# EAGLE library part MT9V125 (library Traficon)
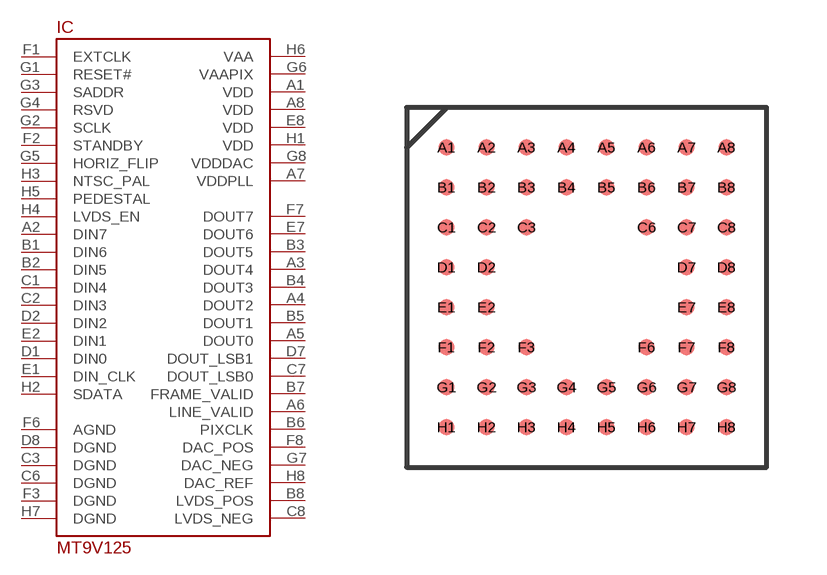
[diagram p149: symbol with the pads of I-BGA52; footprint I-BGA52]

Designator prefix IC

## MT9V125  [I-BGA52]
A1  VDD  pwr
A2  DIN7  in
A3  DOUT4  out
A4  DOUT2  out
A5  DOUT0  out
A6  LINE_VALID  out
A7  VDDPLL  pwr
A8  VDD  pwr
B1  DIN6  in
B2  DIN5  in
B3  DOUT5  out
B4  DOUT3  out
B5  DOUT1  out
B6  PIXCLK  out
B7  FRAME_VALID  out
B8  LVDS_POS  out
C1  DIN4  in
C2  DIN3  in
C3  DGND  pwr
C6  DGND  pwr
C7  DOUT_LSB0  out
C8  LVDS_NEG  out
D1  DIN0  in
D2  DIN2  in
D7  DOUT_LSB1  out
D8  DGND  pwr
E1  DIN_CLK  in
E2  DIN1  in
E7  DOUT6  out
E8  VDD  pwr
F1  EXTCLK  in
F2  STANDBY  in
F3  DGND  pwr
F6  AGND  pwr
F7  DOUT7  out
F8  DAC_POS  out
G1  RESET#  in
G2  SCLK  in
G3  SADDR  in
G4  RSVD  in
G5  HORIZ_FLIP  in
G6  VAAPIX  pwr
G7  DAC_NEG  out
G8  VDDDAC  pwr
H1  VDD  pwr
H2  SDATA  in
H3  NTSC_PAL  in
H4  LVDS_EN  in
H5  PEDESTAL  in
H6  VAA  pwr
H7  DGND  pwr
H8  DAC_REF  out

## Footprint I-BGA52 (pad centres in mm)
smd 0.4 x 0.4: A1 -3.5,3.5; A2 -2.5,3.5; A3 -1.5,3.5; A4 -0.5,3.5; A5 0.5,3.5; A6 1.5,3.5; A7 2.5,3.5; A8 3.5,3.5; B1 -3.5,2.5; B2 -2.5,2.5; B3 -1.5,2.5; B4 -0.5,2.5; B5 0.5,2.5; B6 1.5,2.5; B7 2.5,2.5; B8 3.5,2.5; C1 -3.5,1.5; C2 -2.5,1.5; C3 -1.5,1.5; C6 1.5,1.5; C7 2.5,1.5; C8 3.5,1.5; D1 -3.5,0.5; D2 -2.5,0.5; D7 2.5,0.5; D8 3.5,0.5; E1 -3.5,-0.5; E2 -2.5,-0.5; E7 2.5,-0.5; E8 3.5,-0.5; F1 -3.5,-1.5; F2 -2.5,-1.5; F3 -1.5,-1.5; F6 1.5,-1.5; F7 2.5,-1.5; F8 3.5,-1.5; G1 -3.5,-2.5; G2 -2.5,-2.5; G3 -1.5,-2.5; G4 -0.5,-2.5; G5 0.5,-2.5; G6 1.5,-2.5; G7 2.5,-2.5; G8 3.5,-2.5; H1 -3.5,-3.5; H2 -2.5,-3.5; H3 -1.5,-3.5; H4 -0.5,-3.5; H5 0.5,-3.5; H6 1.5,-3.5; H7 2.5,-3.5; H8 3.5,-3.5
